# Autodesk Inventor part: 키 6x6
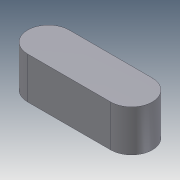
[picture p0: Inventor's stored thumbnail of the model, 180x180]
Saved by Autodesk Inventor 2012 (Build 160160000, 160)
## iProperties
Company: 한국ATC센터
Created: 2013-01
Part Number: 키 6x6
Document SubType Name: Modeling
Designer: KYOUNG IL JANG
Density: 7.25 g/cm^3
Material: 주철
Mass: 4.36193 g
Surface Area: 4.57646 cm^2
Volume: 0.601646 cm^3
Author: KYOUNG IL JANG
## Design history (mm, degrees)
sketch "스케치1"
  geometry: L1 (-6, -3)-(6, -3); L2 (6, 3)-(-6, 3); A1 r 3 centre (6, 0) between (6, -3) and (6, 3); A2 r 3 centre (-6, 0) between (-6, 3) and (-6, -3); 2 further points
  constraints: 4 end point, 4 point on circle, 4 tangent, 2 centre point, 1 horizontal, 1 horizontal alignment, 1 midpoint, 1 parallel, 1 vertical alignment
  dimensions: "d0" = 18 dimension on A1 A2; "d1" = 6 distance between parallel lines of L1 L2
extrude "돌출1" new body sketch "스케치1" stored distance "d2" = 6; taper "d3" = 0 deg
node "솔리드1"
